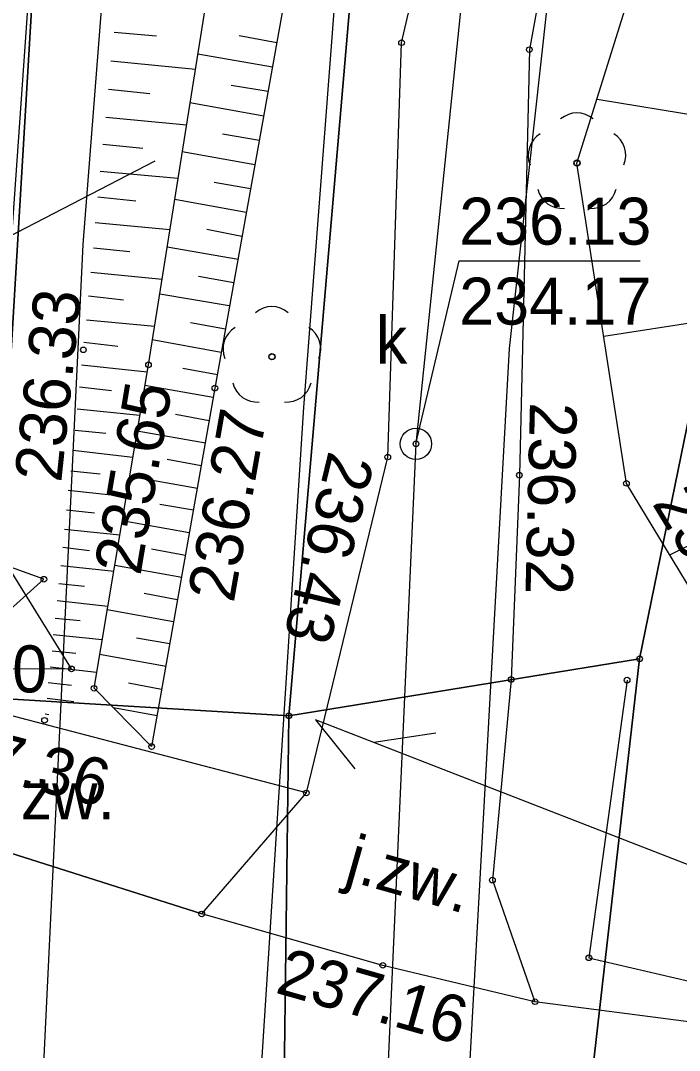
# Model space of a CAD drawing. Extents: x 6596400 to 6597200, y 5539751 to 5540251.
# Drawn here: x 6596715.14 to 6596725.66, y 5540094.36 to 5540110.79 of the extents above; entities that cross this region are included whole.
import ezdxf

# ---------------------------------------------------------------- set-up
doc = ezdxf.new("R2010")
doc.units = 0
for name, color, linetype in [('000 Inne (niezydentyfikowane)', 7, 'Continuous'), ('140-Punkty robocze', 7, 'Continuous'), ('203-punkt graniczny', 7, 'Continuous'), ('218-kontur użytku gruntowego', 7, 'Continuous'), ('219-działka ewidencyjna', 7, 'Continuous'), ('bariera ochronna', 7, 'Continuous'), ('drzewo liściaste', 7, 'Continuous'), ('inny obiekt zagospodarowania terenu', 7, 'Continuous'), ('jezdnia', 7, 'Continuous'), ('jezdnia-Atr17', 7, 'Continuous'), ('Linia obszaru zagospodarowania terenu', 7, 'Continuous'), ('obszar utwardzony', 7, 'Continuous'), ('obszar utwardzony-Atr17', 7, 'Continuous'), ('ogrodzenie trwałe', 7, 'Continuous'), ('Opis obszaru zagospodarowania terenu', 7, 'Continuous'), ('pikieta sztuczna', 7, 'Continuous'), ('pikieta sztuczna-Atr2', 7, 'Continuous'), ('przewód kanalizacyjny', 7, 'Continuous'), ('przewód kanalizacyjny-Atr1', 7, 'Continuous'), ('przewód telekomunikacyjny napowietrzny', 7, 'Continuous'), ('rzedna', 7, 'Continuous'), ('rzedna-Atr2', 7, 'Continuous'), ('rzedna-Atr3', 7, 'Continuous'), ('skarpa nieumocniona', 7, 'Continuous'), ('właz do komory lub kanału - okrągły', 7, 'Continuous'), ('właz do komory lub kanału - okrągły-Atr17', 7, 'Continuous')]:
    doc.layers.add(name, color=color, linetype=linetype)

# ---------------------------------------------------------------- blocks, each defined once
blk = doc.blocks.new('203')
blk.add_circle((0, 0), 0.045)
blk = doc.blocks.new('SUTP')
for p, q in [((0, 0), (0.866, 0.5)), ((9.232, 0), (8.366, 0.5)), ((0, 0), (9.232, 0)), ((1.866, -0.5), (1, 0)), ((7.366, -0.5), (8.232, 0))]:
    blk.add_line(p, q)
blk = doc.blocks.new('US22')
blk.add_circle((0, 0), 0.25)
blk = doc.blocks.new('PW01')
blk.add_circle((0, 0), 0.045)
blk = doc.blocks.new('OP021')
blk.add_circle((0, 0), 0.05)
for centre, start, end in [((0, 0.4), 49.272, 130.728), ((-0.38, 0.124), 121.308, 202.548), ((0.38, 0.124), 337.452, 58.692), ((-0.235, -0.324), 193.221, 274.871), ((0.235, -0.324), 265.129, 346.779)]:
    blk.add_arc(centre, 0.4, start, end)
blk = doc.blocks.new('PIKIETA')
blk.add_circle((0, 0), 0.045)

msp = doc.modelspace()

# ---------------------------------------------------------------- linework, layer by layer
at = {"layer": '000 Inne (niezydentyfikowane)'}
for p, q in [((6596716.63, 5540110.61), (6596717.31, 5540110.55)), ((6596719.23, 5540110.44), (6596718.63, 5540110.55)), ((6596719.16, 5540110.05), (6596717.97, 5540110.26)), ((6596716.58, 5540110.15), (6596717.93, 5540110.02)), ((6596716.54, 5540109.7), (6596717.2, 5540109.63)), ((6596719.09, 5540109.66), (6596718.5, 5540109.76)), ((6596724.34, 5540109.54), (6596736.01, 5540107.62)), ((6596719.02, 5540109.27), (6596717.84, 5540109.48)), ((6596716.5, 5540109.25), (6596717.79, 5540109.13)), ((6596718.95, 5540108.88), (6596718.36, 5540108.98)), ((6596716.45, 5540108.82), (6596717.09, 5540108.76)), ((6596718.88, 5540108.49), (6596717.72, 5540108.7)), ((6596716.41, 5540108.39), (6596717.65, 5540108.28)), ((6596718.81, 5540108.11), (6596718.23, 5540108.21)), ((6596716.37, 5540107.98), (6596716.98, 5540107.92)), ((6596718.74, 5540107.73), (6596717.6, 5540107.94)), ((6596716.33, 5540107.57), (6596717.52, 5540107.46)), ((6596718.67, 5540107.35), (6596718.11, 5540107.46)), ((6596725.5, 5540102.27), (6596736, 5540107.48)), ((6596716.3, 5540107.17), (6596716.88, 5540107.11)), ((6596718.61, 5540106.98), (6596717.48, 5540107.18)), ((6596716.26, 5540106.78), (6596717.4, 5540106.67)), ((6596718.54, 5540106.61), (6596717.98, 5540106.71)), ((6596724.45, 5540105.76), (6596730.23, 5540106.66)), ((6596716.22, 5540106.4), (6596716.78, 5540106.34)), ((6596718.47, 5540106.24), (6596717.36, 5540106.43)), ((6596716.19, 5540106.02), (6596717.28, 5540105.92)), ((6596718.41, 5540105.87), (6596717.85, 5540105.97)), ((6596716.15, 5540105.66), (6596716.69, 5540105.6)), ((6596718.34, 5540105.5), (6596717.24, 5540105.7)), ((6596716.11, 5540105.3), (6596717.16, 5540105.19)), ((6596718.28, 5540105.14), (6596717.73, 5540105.24)), ((6596716.08, 5540104.95), (6596716.59, 5540104.89)), ((6596718.21, 5540104.78), (6596717.12, 5540104.97)), ((6596716.04, 5540104.6), (6596717.04, 5540104.5)), ((6596718.15, 5540104.41), (6596717.61, 5540104.51)), ((6596716.01, 5540104.26), (6596716.5, 5540104.21)), ((6596718.09, 5540104.05), (6596717, 5540104.24)), ((6596715.97, 5540103.94), (6596716.93, 5540103.83)), ((6596718.02, 5540103.69), (6596717.48, 5540103.79)), ((6596715.94, 5540103.61), (6596716.41, 5540103.56)), ((6596717.96, 5540103.33), (6596716.88, 5540103.52)), ((6596715.9, 5540103.3), (6596716.83, 5540103.2)), ((6596715.87, 5540102.99), (6596716.32, 5540102.94)), ((6596717.9, 5540102.98), (6596717.36, 5540103.07)), ((6596717.83, 5540102.62), (6596716.76, 5540102.81)), ((6596715.84, 5540102.68), (6596716.72, 5540102.59)), ((6596715.81, 5540102.39), (6596716.24, 5540102.34)), ((6596717.77, 5540102.26), (6596717.23, 5540102.36)), ((6596715.78, 5540102.1), (6596716.63, 5540102.01)), ((6596717.71, 5540101.91), (6596716.64, 5540102.1)), ((6596715.75, 5540101.81), (6596716.16, 5540101.77)), ((6596717.64, 5540101.55), (6596717.11, 5540101.65)), ((6596715.72, 5540101.54), (6596716.53, 5540101.45)), ((6596717.58, 5540101.2), (6596716.52, 5540101.39)), ((6596715.69, 5540101.26), (6596716.09, 5540101.22)), ((6596715.66, 5540101), (6596716.44, 5540100.92)), ((6596717.52, 5540100.85), (6596716.99, 5540100.94)), ((6596715.64, 5540100.74), (6596716.02, 5540100.7)), ((6596717.46, 5540100.49), (6596716.4, 5540100.68)), ((6596715.61, 5540100.48), (6596716.35, 5540100.4)), ((6596715.58, 5540100.23), (6596715.95, 5540100.19)), ((6596717.39, 5540100.12), (6596716.86, 5540100.22)), ((6596715.56, 5540099.98), (6596715.99, 5540099.93)), ((6596717.32, 5540099.7), (6596716.62, 5540099.83)), ((6596715.53, 5540099.73), (6596715.59, 5540099.72))]:
    msp.add_line(p, q, dxfattribs=at)
at = {"layer": '218-kontur użytku gruntowego'}
for points in [[(6596721.251, 5540121.028), (6596719.42, 5540099.7)], [(6596719.42, 5540099.7), (6596721.251, 5540121.028)], [(6596714.65, 5540099.99), (6596715.907, 5540120.962)], [(6596715.907, 5540120.962), (6596714.65, 5540099.99)], [(6596727.34, 5540111.95), (6596725.02, 5540100.61)], [(6596725.02, 5540100.61), (6596727.34, 5540111.95)], [(6596725.02, 5540100.61), (6596719.42, 5540099.7)], [(6596719.42, 5540099.7), (6596725.02, 5540100.61)], [(6596725.02, 5540100.61), (6596724.03, 5540091.92)], [(6596724.03, 5540091.92), (6596725.02, 5540100.61)], [(6596719.42, 5540099.7), (6596714.65, 5540099.99)], [(6596714.65, 5540099.99), (6596719.42, 5540099.7)], [(6596719.42, 5540099.7), (6596719.21, 5540083.11)], [(6596719.21, 5540083.11), (6596719.42, 5540099.7)]]:
    msp.add_lwpolyline(points, dxfattribs=at)
at = {"layer": '219-działka ewidencyjna'}
for points in [[(6596719.42, 5540099.7), (6596721.251, 5540121.028)], [(6596714.65, 5540099.99), (6596715.907, 5540120.962)], [(6596725.02, 5540100.61), (6596727.34, 5540111.95)], [(6596719.42, 5540099.7), (6596725.02, 5540100.61)], [(6596724.03, 5540091.92), (6596725.02, 5540100.61)], [(6596714.65, 5540099.99), (6596719.42, 5540099.7)], [(6596719.21, 5540083.11), (6596719.42, 5540099.7)]]:
    msp.add_lwpolyline(points, dxfattribs=at)
at = {"layer": 'bariera ochronna'}
msp.add_lwpolyline([(6596724.82, 5540100.27), (6596724.21, 5540095.84), (6596728.33, 5540094.88), (6596750, 5540090.55), (6596759.32, 5540088.76), (6596768.42, 5540087.04), (6596777.66, 5540085.28), (6596786.8, 5540083.5), (6596789.01, 5540083.12), (6596792.87, 5540082.26), (6596795.36, 5540081.78), (6596800.78, 5540080.9), (6596809.14, 5540079.91)], dxfattribs=at)
at = {"layer": 'inny obiekt zagospodarowania terenu'}
msp.add_lwpolyline([(6596714.78, 5540102.14), (6596714.92, 5540101.35), (6596715.51, 5540101.88)], close=True, dxfattribs=at)
at = {"layer": 'jezdnia'}
for points in [[(6596728.26, 5540094.5), (6596723.35, 5540095.14), (6596720.92, 5540095.72), (6596718.03, 5540096.54), (6596712.8, 5540098.2), (6596708.8, 5540099.55), (6596704.7, 5540101.24), (6596694.34, 5540105.7), (6596683.34, 5540111.32), (6596679.35, 5540113.39), (6596672.62, 5540117.3), (6596666.82, 5540120.65), (6596657.79, 5540125.88), (6596655.967, 5540126.802)], [(6596725.521, 5540121.08), (6596724.07, 5540114.79), (6596723.26, 5540110.33), (6596723.1, 5540103.54), (6596722.97, 5540100.28), (6596722.67, 5540097.08), (6596723.35, 5540095.14), (6596720.92, 5540095.72), (6596718.03, 5540096.54)], [(6596718.03, 5540096.54), (6596719.7, 5540098.47), (6596721, 5540103.83), (6596721.22, 5540110.44), (6596722.35, 5540115.3), (6596723.751, 5540121.058)]]:
    msp.add_lwpolyline(points, dxfattribs=at)
at = {"layer": 'Linia obszaru zagospodarowania terenu'}
for points in [[(6596718.63, 5540088.53), (6596719.66, 5540104.62), (6596720.915, 5540121.024)], [(6596717.208, 5540120.978), (6596716.13, 5540107.22), (6596715.39, 5540091.82)]]:
    msp.add_lwpolyline(points, dxfattribs=at)
at = {"layer": 'obszar utwardzony'}
msp.add_lwpolyline([(6596713.73, 5540100.03), (6596712.8, 5540098.2), (6596718.03, 5540096.54), (6596719.7, 5540098.47)], close=True, dxfattribs=at)
at = {"layer": 'ogrodzenie trwałe'}
msp.add_lwpolyline([(6596714.61, 5540101.89), (6596715.7, 5540117.35), (6596715.95, 5540120.963)], dxfattribs=at)
at = {"layer": 'Opis obszaru zagospodarowania terenu'}
msp.add_lwpolyline([(6596717.28, 5540108.55), (6596714.34, 5540107.03), (6596709.408, 5540107.03)], dxfattribs=at)
at = {"layer": 'przewód kanalizacyjny'}
for points in [[(6596652.409, 5540119.314), (6596659.51, 5540115.47), (6596667.73, 5540121.28), (6596680.3, 5540113.87), (6596707.99, 5540100.58), (6596711.34, 5540100.47), (6596715.95, 5540100.45)], [(6596723.203, 5540121.052), (6596721.45, 5540104.04), (6596720.5, 5540082.91), (6596720.2, 5540067.11), (6596715.44, 5540062.371)], [(6596724.65, 5540121.069), (6596722.94, 5540105.56), (6596720.82, 5540067.29), (6596715.895, 5540061.995)]]:
    msp.add_lwpolyline(points, dxfattribs=at)
at = {"layer": 'rzedna-Atr2'}
for points in [[(6596721.45, 5540104.04), (6596722.14, 5540106.96), (6596725.031, 5540106.96)], [(6596715.95, 5540100.45), (6596714.46, 5540102.85), (6596711.346, 5540102.85)]]:
    msp.add_lwpolyline(points, dxfattribs=at)
at = {"layer": 'skarpa nieumocniona'}
for points in [[(6596751.79, 5540118.27), (6596760.37, 5540114.69), (6596748.71, 5540116.3), (6596743.9, 5540116.21), (6596740.41, 5540117.83), (6596735.6, 5540111.55), (6596736.12, 5540109.87), (6596735.55, 5540098.25), (6596728.64, 5540097.09), (6596724.81, 5540103.41), (6596724.02, 5540108.52), (6596725.61, 5540113.6), (6596728.6, 5540116.52), (6596734.94, 5540121.2), (6596745.21, 5540121.32)], [(6596751.79, 5540118.27), (6596760.37, 5540114.69), (6596748.71, 5540116.3), (6596743.9, 5540116.21), (6596740.41, 5540117.83), (6596735.6, 5540111.55), (6596736.12, 5540109.87), (6596735.55, 5540098.25), (6596728.64, 5540097.09), (6596724.81, 5540103.41), (6596724.02, 5540108.52), (6596725.61, 5540113.6), (6596728.6, 5540116.52), (6596734.94, 5540121.2), (6596745.21, 5540121.32)], [(6596720.42, 5540117.1), (6596718.24, 5540104.93), (6596717.23, 5540099.21), (6596716.31, 5540100.14), (6596717.18, 5540105.3), (6596719.11, 5540117.43), (6596719.5, 5540121.01), (6596720.91, 5540121.02)], [(6596720.42, 5540117.1), (6596718.24, 5540104.93), (6596717.23, 5540099.21), (6596716.31, 5540100.14), (6596717.18, 5540105.3), (6596719.11, 5540117.43), (6596719.5, 5540121.01), (6596720.91, 5540121.02)]]:
    msp.add_lwpolyline(points, close=True, dxfattribs=at)

# ---------------------------------------------------------------- block references
at = {"layer": '140-Punkty robocze'}
for p in [(6596721.22, 5540110.44), (6596723.26, 5540110.33), (6596724.02, 5540108.52), (6596716.14, 5540105.54), (6596719.15, 5540105.43), (6596717.18, 5540105.3), (6596718.24, 5540104.93), (6596721, 5540103.83), (6596723.1, 5540103.54), (6596724.81, 5540103.41), (6596715.51, 5540101.88), (6596715.95, 5540100.45), (6596722.97, 5540100.28), (6596716.31, 5540100.14), (6596724.82, 5540100.27), (6596715.52, 5540099.63), (6596717.23, 5540099.21), (6596719.7, 5540098.47), (6596722.67, 5540097.08), (6596718.03, 5540096.54), (6596724.21, 5540095.84), (6596723.35, 5540095.14)]:
    msp.add_blockref('PIKIETA', p, dxfattribs=at)
at = {"layer": '203-punkt graniczny'}
for p in [(6596725.02, 5540100.61), (6596719.42, 5540099.7)]:
    msp.add_blockref('203', p, dxfattribs=at)
at = {"layer": 'drzewo liściaste'}
for p in [(6596724.02, 5540108.52), (6596719.15, 5540105.43)]:
    msp.add_blockref('OP021', p, dxfattribs=at)
at = {"layer": 'pikieta sztuczna'}
for p in [(6596716.14, 5540105.54), (6596717.18, 5540105.3), (6596718.24, 5540104.93), (6596721, 5540103.83), (6596723.1, 5540103.54), (6596724.81, 5540103.41), (6596720.92, 5540095.72)]:
    msp.add_blockref('PW01', p, dxfattribs=at)
at = {"layer": 'przewód telekomunikacyjny napowietrzny', "rotation": 158.745}
msp.add_blockref('SUTP', (6596728.45, 5540096.29), dxfattribs=at)
at = {"layer": 'rzedna'}
for p in [(6596721.45, 5540104.04), (6596715.95, 5540100.45)]:
    msp.add_blockref('PW01', p, dxfattribs=at)
at = {"layer": 'właz do komory lub kanału - okrągły'}
msp.add_blockref('US22', (6596721.45, 5540104.04), dxfattribs=at)

# ---------------------------------------------------------------- texts
at = {"layer": 'jezdnia-Atr17'}
msp.add_text('j.zw.', height=0.75, rotation=344.159, dxfattribs=at).set_placement((6596720.29, 5540097.09))
msp.add_text('j.zw.', height=0.75, rotation=344.159, dxfattribs=at).set_placement((6596720.29, 5540097.09))
at = {"layer": 'obszar utwardzony-Atr17'}
msp.add_text('zw.', height=0.75, dxfattribs=at).set_placement((6596715.14, 5540098.05))
at = {"layer": 'pikieta sztuczna-Atr2'}
for s, rotation, p in [('236.33', 84.011, (6596715.786, 5540103.412)), ('235.65', 80.43, (6596717.05, 5540101.925)), ('236.27', 79.986, (6596718.539, 5540101.49)), ('236.32', 268.65, (6596723.27, 5540104.708)), ('236.43', 256.367, (6596720.061, 5540103.947)), ('236.15', 301.216, (6596725.209, 5540103.091)), ('237.36', 345.356, (6596713.47, 5540099.014)), ('237.16', 344.159, (6596719.185, 5540095.288))]:
    msp.add_text(s, height=0.75, rotation=rotation, dxfattribs=at).set_placement(p)
at = {"layer": 'przewód kanalizacyjny-Atr1'}
msp.add_text('kd400', height=0.75, rotation=359.751, dxfattribs=at).set_placement((6596712.828, 5540100.085))
at = {"layer": 'rzedna-Atr2'}
msp.add_text('236.13', height=0.75, dxfattribs=at).set_placement((6596722.14, 5540107.218))
at = {"layer": 'rzedna-Atr3'}
msp.add_text('234.17', height=0.75, dxfattribs=at).set_placement((6596722.14, 5540105.942))
at = {"layer": 'właz do komory lub kanału - okrągły-Atr17'}
msp.add_text('k', height=0.75, dxfattribs=at).set_placement((6596720.81, 5540105.32))

doc.saveas('drawing.dxf')
